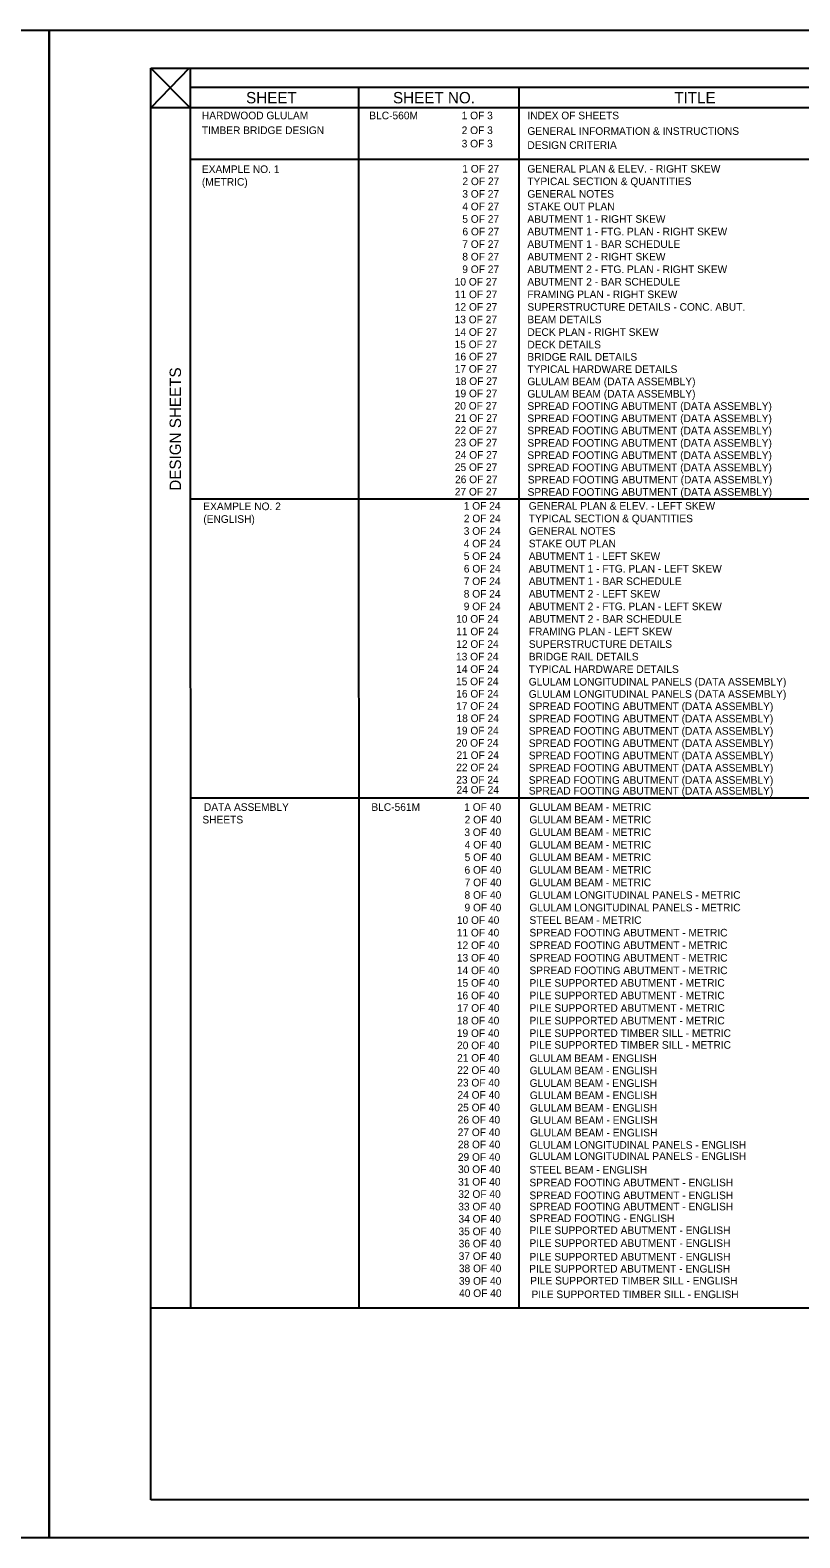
# Model space of a CAD drawing. Extents: x 637594 to 640253, y 297247 to 298527.
# Drawn here: x 638428 to 638731, y 297247 to 297841 of the extents above; entities that cross this region are included whole.
import ezdxf

# ---------------------------------------------------------------- set-up
doc = ezdxf.new("R2010")
doc.units = 0
for name, color, linetype in [('2', 7, 'Continuous'), ('4', 7, 'Continuous'), ('6', 7, 'Continuous'), ('PLT-BNDY', 7, 'Continuous')]:
    doc.layers.add(name, color=color, linetype=linetype)

msp = doc.modelspace()

# ---------------------------------------------------------------- linework, layer by layer
at = {"layer": '2'}
for p, q in [((638475.46, 297262.46), (638475.46, 297826.46)), ((638475.46, 297826.46), (639261.46, 297826.46)), ((639261.46, 297262.46), (638475.46, 297262.46))]:
    msp.add_line(p, q, dxfattribs=at)
at = {"layer": '4'}
for p, q in [((638475.46, 297826.46), (638491.02, 297810.83)), ((638490.54, 297826.46), (638475.46, 297810.83)), ((638491.02, 297826.46), (638491.1, 297337.94)), ((638557.3, 297818.89), (638557.38, 297337.94)), ((638620.35, 297818.89), (638620.43, 297337.94)), ((638788.71, 297810.83), (638475.46, 297810.83)), ((638762.01, 297790.44), (638491.02, 297790.44)), ((638762.04, 297656.66), (638491.1, 297656.66)), ((638762.09, 297538.86), (638491.1, 297538.86)), ((638762.09, 297337.94), (638475.46, 297337.94))]:
    msp.add_line(p, q, dxfattribs=at)
at = {"layer": '6'}
msp.add_line((639044.75, 297818.89), (638491.02, 297818.89), dxfattribs=at)
at = {"layer": 'PLT-BNDY'}
for points in [[(637594.46, 297841.46), (638435.46, 297841.46), (638435.46, 297247.46), (637594.46, 297247.46)], [(638435.46, 297841.46), (639276.46, 297841.46), (639276.46, 297247.46), (638435.46, 297247.46)]]:
    msp.add_lwpolyline(points, close=True, dxfattribs=at)

# ---------------------------------------------------------------- texts
at = {"layer": '2'}
for s, height, p in [('SHEET', 4.479, (638512.98, 297812.62)), ('SHEET NO.', 4.479, (638570.85, 297812.62)), ('TITLE', 4.479, (638681.62, 297812.62)), ('HARDWOOD GLULAM', 3.0001, (638495.58, 297806.34)), ('BLC-560M', 3, (638561.51, 297806.34)), ('1 OF 3', 3, (638597.89, 297806.34)), ('INDEX OF SHEETS', 3.0001, (638623.76, 297806.34)), ('TIMBER BRIDGE DESIGN', 3.0001, (638495.58, 297800.52)), ('2 OF 3', 3, (638597.89, 297800.52)), ('GENERAL INFORMATION & INSTRUCTIONS', 3.0001, (638623.76, 297800.21)), ('3 OF 3', 3, (638597.89, 297795.26)), ('DESIGN CRITERIA', 3.0001, (638623.76, 297794.66)), ('EXAMPLE NO. 1', 3.0001, (638495.58, 297785.18)), ('1 OF 27', 3, (638598.14, 297785.35)), ('GENERAL PLAN & ELEV. - RIGHT SKEW', 3.0001, (638623.76, 297785.35)), ('(METRIC)', 3, (638495.58, 297780.18)), ('3 OF 27', 3, (638598.14, 297775.46)), ('2 OF 27', 3, (638598.19, 297780.4)), ('TYPICAL SECTION & QUANTITIES', 3.0001, (638623.76, 297780.4)), ('GENERAL NOTES', 3.0001, (638623.76, 297775.46)), ('4 OF 27', 3, (638598.14, 297770.51)), ('STAKE OUT PLAN', 3.0001, (638623.76, 297770.51)), ('5 OF 27', 3, (638598.14, 297765.56)), ('ABUTMENT 1 - RIGHT SKEW', 3.0001, (638623.76, 297765.56)), ('6 OF 27', 3, (638598.19, 297760.61)), ('ABUTMENT 1 - FTG. PLAN - RIGHT SKEW', 3.0001, (638623.76, 297760.61)), ('7 OF 27', 3, (638598.14, 297755.66)), ('ABUTMENT 1 - BAR SCHEDULE', 3.0001, (638623.76, 297755.66)), ('8 OF 27', 3, (638598.14, 297750.71)), ('9 OF 27', 3, (638598.14, 297745.76)), ('ABUTMENT 2 - RIGHT SKEW', 3.0001, (638623.76, 297750.71)), ('ABUTMENT 2 - FTG. PLAN - RIGHT SKEW', 3.0001, (638623.76, 297745.76)), ('10 OF 27', 3, (638595.14, 297740.82)), ('ABUTMENT 2 - BAR SCHEDULE', 3.0001, (638623.76, 297740.82)), ('11 OF 27', 3, (638595.19, 297735.87)), ('FRAMING PLAN - RIGHT SKEW', 3.0001, (638623.76, 297735.87)), ('12 OF 27', 3, (638595.19, 297730.92)), ('SUPERSTRUCTURE DETAILS - CONC. ABUT.', 3.0001, (638623.76, 297730.92)), ('13 OF 27', 3, (638595.1, 297725.97)), ('BEAM DETAILS', 3.0001, (638623.76, 297725.97)), ('15 OF 27', 3, (638595.1, 297716.18)), ('14 OF 27', 3, (638595.14, 297721.02)), ('DECK PLAN - RIGHT SKEW', 3.0001, (638623.76, 297721.02)), ('DECK DETAILS', 3.0001, (638623.76, 297716.08)), ('16 OF 27', 3, (638595.19, 297711.34)), ('BRIDGE RAIL DETAILS', 3.0001, (638623.76, 297711.24)), ('17 OF 27', 3, (638595.14, 297706.5)), ('TYPICAL HARDWARE DETAILS', 3.0001, (638623.76, 297706.4)), ('18 OF 27', 3, (638595.29, 297701.66)), ('GLULAM BEAM (DATA ASSEMBLY)', 3.0001, (638623.76, 297701.55)), ('20 OF 27', 3, (638595.1, 297691.98)), ('19 OF 27', 3, (638595.19, 297696.82)), ('SPREAD FOOTING ABUTMENT (DATA ASSEMBLY)', 3.0001, (638623.76, 297691.87)), ('GLULAM BEAM (DATA ASSEMBLY)', 3.0001, (638623.76, 297696.71)), ('21 OF 27', 3, (638595.29, 297687.14)), ('SPREAD FOOTING ABUTMENT (DATA ASSEMBLY)', 3.0001, (638623.76, 297687.03)), ('22 OF 27', 3, (638595.19, 297682.3)), ('SPREAD FOOTING ABUTMENT (DATA ASSEMBLY)', 3.0001, (638623.76, 297682.19)), ('23 OF 27', 3, (638595.19, 297677.46)), ('SPREAD FOOTING ABUTMENT (DATA ASSEMBLY)', 3.0001, (638623.76, 297677.35)), ('24 OF 27', 3, (638595.28, 297672.62)), ('SPREAD FOOTING ABUTMENT (DATA ASSEMBLY)', 3.0001, (638623.76, 297672.51)), ('25 OF 27', 3, (638595.19, 297667.78)), ('26 OF 27', 3, (638595.27, 297662.97)), ('SPREAD FOOTING ABUTMENT (DATA ASSEMBLY)', 3.0001, (638623.76, 297667.67)), ('SPREAD FOOTING ABUTMENT (DATA ASSEMBLY)', 3.0001, (638623.93, 297662.86)), ('27 OF 27', 3, (638595.18, 297658.12)), ('SPREAD FOOTING ABUTMENT (DATA ASSEMBLY)', 3.0001, (638623.84, 297658.01)), ('EXAMPLE NO. 2', 3.0001, (638496.14, 297652.35)), ('1 OF 24', 3, (638598.71, 297652.53)), ('GENERAL PLAN & ELEV. - LEFT SKEW', 3.0001, (638624.32, 297652.53)), ('(ENGLISH)', 3, (638496.14, 297647.35)), ('2 OF 24', 3, (638598.75, 297647.58)), ('TYPICAL SECTION & QUANTITIES', 3.0001, (638624.32, 297647.58)), ('3 OF 24', 3, (638598.71, 297642.63)), ('GENERAL NOTES', 3.0001, (638624.32, 297642.63)), ('4 OF 24', 3, (638598.71, 297637.68)), ('5 OF 24', 3, (638598.71, 297632.73)), ('ABUTMENT 1 - LEFT SKEW', 3.0001, (638624.32, 297632.73)), ('STAKE OUT PLAN', 3.0001, (638624.32, 297637.68)), ('6 OF 24', 3, (638598.75, 297627.78)), ('ABUTMENT 1 - FTG. PLAN - LEFT SKEW', 3.0001, (638624.32, 297627.78)), ('7 OF 24', 3, (638598.71, 297622.84)), ('ABUTMENT 1 - BAR SCHEDULE', 3.0001, (638624.32, 297622.84)), ('8 OF 24', 3, (638598.71, 297617.89)), ('ABUTMENT 2 - LEFT SKEW', 3.0001, (638624.32, 297617.89)), ('9 OF 24', 3, (638598.71, 297612.94)), ('ABUTMENT 2 - FTG. PLAN - LEFT SKEW', 3.0001, (638624.32, 297612.94)), ('10 OF 24', 3, (638595.71, 297607.99)), ('11 OF 24', 3, (638595.75, 297603.04)), ('ABUTMENT 2 - BAR SCHEDULE', 3.0001, (638624.32, 297607.99)), ('FRAMING PLAN - LEFT SKEW', 3.0001, (638624.32, 297603.04)), ('12 OF 24', 3, (638595.75, 297598.1)), ('SUPERSTRUCTURE DETAILS', 3.0001, (638624.32, 297598.1)), ('13 OF 24', 3, (638595.66, 297593.15)), ('BRIDGE RAIL DETAILS', 3.0001, (638624.32, 297593.15)), ('14 OF 24', 3, (638595.71, 297588.2)), ('TYPICAL HARDWARE DETAILS', 3.0001, (638624.32, 297588.2)), ('15 OF 24', 3, (638595.66, 297583.36)), ('GLULAM LONGITUDINAL PANELS (DATA ASSEMBLY)', 3.0001, (638624.32, 297583.25)), ('17 OF 24', 3, (638595.71, 297573.68)), ('16 OF 24', 3, (638595.75, 297578.52)), ('SPREAD FOOTING ABUTMENT (DATA ASSEMBLY)', 3.0001, (638624.32, 297573.57)), ('GLULAM LONGITUDINAL PANELS (DATA ASSEMBLY)', 3.0001, (638624.32, 297578.41)), ('18 OF 24', 3, (638595.85, 297568.84)), ('SPREAD FOOTING ABUTMENT (DATA ASSEMBLY)', 3.0001, (638624.32, 297568.73)), ('19 OF 24', 3, (638595.76, 297564)), ('SPREAD FOOTING ABUTMENT (DATA ASSEMBLY)', 3.0001, (638624.32, 297563.89)), ('20 OF 24', 3, (638595.66, 297559.16)), ('SPREAD FOOTING ABUTMENT (DATA ASSEMBLY)', 3.0001, (638624.32, 297559.05)), ('22 OF 24', 3, (638595.76, 297549.47)), ('21 OF 24', 3, (638595.85, 297554.32)), ('SPREAD FOOTING ABUTMENT (DATA ASSEMBLY)', 3.0001, (638624.32, 297554.21)), ('SPREAD FOOTING ABUTMENT (DATA ASSEMBLY)', 3.0001, (638624.32, 297549.37)), ('23 OF 24', 3, (638595.76, 297544.63)), ('SPREAD FOOTING ABUTMENT (DATA ASSEMBLY)', 3.0001, (638624.32, 297544.53)), ('24 OF 24', 3, (638595.85, 297540.69)), ('SPREAD FOOTING ABUTMENT (DATA ASSEMBLY)', 3.0001, (638624.32, 297540.3)), ('DATA ASSEMBLY', 3.0001, (638496.39, 297533.87)), ('BLC-561M', 3, (638562.33, 297533.87)), ('1 OF 40', 3, (638598.91, 297533.87)), ('GLULAM BEAM - METRIC', 3.0001, (638624.58, 297533.87)), ('SHEETS', 3, (638495.78, 297528.92)), ('2 OF 40', 3, (638599.07, 297528.92)), ('GLULAM BEAM - METRIC', 3.0001, (638624.58, 297528.92)), ('3 OF 40', 3, (638598.94, 297523.97)), ('GLULAM BEAM - METRIC', 3.0001, (638624.58, 297523.97)), ('4 OF 40', 3, (638599.07, 297519.03)), ('5 OF 40', 3, (638599.07, 297514.08)), ('GLULAM BEAM - METRIC', 3.0001, (638624.58, 297519.03)), ('GLULAM BEAM - METRIC', 3.0001, (638624.58, 297514.08)), ('6 OF 40', 3, (638599.01, 297509.13)), ('GLULAM BEAM - METRIC', 3.0001, (638624.58, 297509.13)), ('7 OF 40', 3, (638599.07, 297504.18)), ('GLULAM BEAM - METRIC', 3.0001, (638624.58, 297504.18)), ('8 OF 40', 3, (638599.01, 297499.23)), ('GLULAM LONGITUDINAL PANELS - METRIC', 3.0001, (638624.58, 297499.23)), ('9 OF 40', 3, (638599.01, 297494.28)), ('GLULAM LONGITUDINAL PANELS - METRIC', 3.0001, (638624.58, 297494.28)), ('11 OF 40', 3, (638595.97, 297484.39)), ('10 OF 40', 3, (638596, 297489.34)), ('STEEL BEAM - METRIC', 3.0001, (638624.58, 297489.34)), ('SPREAD FOOTING ABUTMENT - METRIC', 3.0001, (638624.58, 297484.39)), ('12 OF 40', 3, (638596, 297479.44)), ('SPREAD FOOTING ABUTMENT - METRIC', 3.0001, (638624.58, 297479.44)), ('13 OF 40', 3, (638596, 297474.49)), ('SPREAD FOOTING ABUTMENT - METRIC', 3.0001, (638624.58, 297474.49)), ('14 OF 40', 3, (638596, 297469.54)), ('SPREAD FOOTING ABUTMENT - METRIC', 3.0001, (638624.58, 297469.54)), ('15 OF 40', 3, (638596, 297464.6)), ('PILE SUPPORTED ABUTMENT - METRIC', 3.0001, (638624.58, 297464.6)), ('16 OF 40', 3, (638596, 297459.65)), ('17 OF 40', 3, (638596.07, 297454.7)), ('PILE SUPPORTED ABUTMENT - METRIC', 3.0001, (638624.58, 297459.65)), ('PILE SUPPORTED ABUTMENT - METRIC', 3.0001, (638624.58, 297454.7)), ('18 OF 40', 3, (638596, 297449.75)), ('PILE SUPPORTED ABUTMENT - METRIC', 3.0001, (638624.58, 297449.75)), ('19 OF 40', 3, (638596, 297444.8)), ('PILE SUPPORTED TIMBER SILL - METRIC', 3.0001, (638624.58, 297444.8)), ('20 OF 40', 3, (638596.08, 297439.99)), ('PILE SUPPORTED TIMBER SILL - METRIC', 3.0001, (638624.58, 297440.15)), ('21 OF 40', 3, (638596.08, 297435.04)), ('GLULAM BEAM - ENGLISH', 3.0001, (638624.58, 297434.91)), ('22 OF 40', 3, (638596.16, 297430.23)), ('23 OF 40', 3, (638596.16, 297425.28)), ('GLULAM BEAM - ENGLISH', 3.0001, (638624.66, 297430.09)), ('GLULAM BEAM - ENGLISH', 3.0001, (638624.66, 297425.14)), ('24 OF 40', 3, (638596.24, 297420.46)), ('GLULAM BEAM - ENGLISH', 3.0001, (638624.74, 297420.33)), ('25 OF 40', 3, (638596.24, 297415.51)), ('GLULAM BEAM - ENGLISH', 3.0001, (638624.74, 297415.38)), ('26 OF 40', 3, (638596.32, 297410.7)), ('GLULAM BEAM - ENGLISH', 3.0001, (638624.82, 297410.57)), ('27 OF 40', 3, (638596.32, 297405.75)), ('28 OF 40', 3, (638596.39, 297400.94)), ('GLULAM BEAM - ENGLISH', 3.0001, (638624.82, 297405.62)), ('29 OF 40', 3, (638596.39, 297395.99)), ('GLULAM LONGITUDINAL PANELS - ENGLISH', 3.0001, (638624.58, 297400.76)), ('GLULAM LONGITUDINAL PANELS - ENGLISH', 3.0001, (638624.58, 297396.36)), ('30 OF 40', 3, (638596.47, 297391.17)), ('STEEL BEAM - ENGLISH', 3.0001, (638624.58, 297390.99)), ('31 OF 40', 3, (638596.47, 297386.23)), ('SPREAD FOOTING ABUTMENT - ENGLISH', 3.0001, (638624.58, 297385.94)), ('32 OF 40', 3, (638596.55, 297381.41)), ('SPREAD FOOTING ABUTMENT - ENGLISH', 3.0001, (638624.58, 297380.9)), ('33 OF 40', 3, (638596.55, 297376.46)), ('34 OF 40', 3, (638596.63, 297371.65)), ('SPREAD FOOTING ABUTMENT - ENGLISH', 3.0001, (638624.58, 297376.5)), ('SPREAD FOOTING - ENGLISH', 3.0001, (638624.58, 297371.85)), ('35 OF 40', 3, (638596.63, 297366.7)), ('PILE SUPPORTED ABUTMENT - ENGLISH', 3.0001, (638624.58, 297367.12)), ('36 OF 40', 3, (638596.71, 297361.88)), ('PILE SUPPORTED ABUTMENT - ENGLISH', 3.0001, (638624.58, 297362.08)), ('37 OF 40', 3, (638596.71, 297356.94)), ('PILE SUPPORTED ABUTMENT - ENGLISH', 3.0001, (638624.58, 297356.7)), ('38 OF 40', 3, (638596.79, 297352.12)), ('PILE SUPPORTED ABUTMENT - ENGLISH', 3.0001, (638624.48, 297351.99)), ('39 OF 40', 3, (638596.79, 297347.17)), ('40 OF 40', 3, (638596.87, 297342.36)), ('PILE SUPPORTED TIMBER SILL - ENGLISH', 3.0001, (638624.88, 297347.28)), ('PILE SUPPORTED TIMBER SILL - ENGLISH', 3.0001, (638625.37, 297341.9))]:
    msp.add_text(s, height=height, dxfattribs=at).set_placement(p)
msp.add_text('DESIGN SHEETS', height=4.4794, rotation=90, dxfattribs=at).set_placement((638487.36, 297660))

doc.saveas('drawing.dxf')
